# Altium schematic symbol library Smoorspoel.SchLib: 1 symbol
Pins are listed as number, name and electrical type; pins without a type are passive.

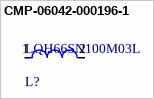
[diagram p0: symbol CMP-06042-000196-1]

## CMP-06042-000196-1
designator L?, comment LQH66SN100M03L
FIXED IND 10UH 1.6A 36 MOHM SMD; Test Frequency: 1MHz; Inductance Tolerance: 20%; Core Material: Ferrite; Self Resonant Frequency: 20MHz; DC Resistance (DCR): 36mR; Shielding: Shielded
footprint FP-LQH66SN_03-MFG
pins: 1, 2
